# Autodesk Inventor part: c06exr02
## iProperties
Created: 2001-12
Part Number: c06exr02
Document SubType Name: Modeling
Control State: 0
Master: False
Checked Out: False
Shininess: 77.0
Angle Display Precision: 2
Document Length Units: 11269
Document Angle Units: 11279
Document Time Units: 11290
Document Mass Units: 11283
Document Length Units Precision: 3
Document Angle Units Precision: 2
Density: 0.0
Volumn: 0.0
Area: 0.0
PropertySet Name: Model Information
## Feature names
1. Extrusion1
2. Extrusion2
3. Extrusion3
4. Extrusion4
5. Extrusion6
6. Hole1
7. Mirror1
8. Fillet1
9. Hole2
10. Hole3
11. Hole4
